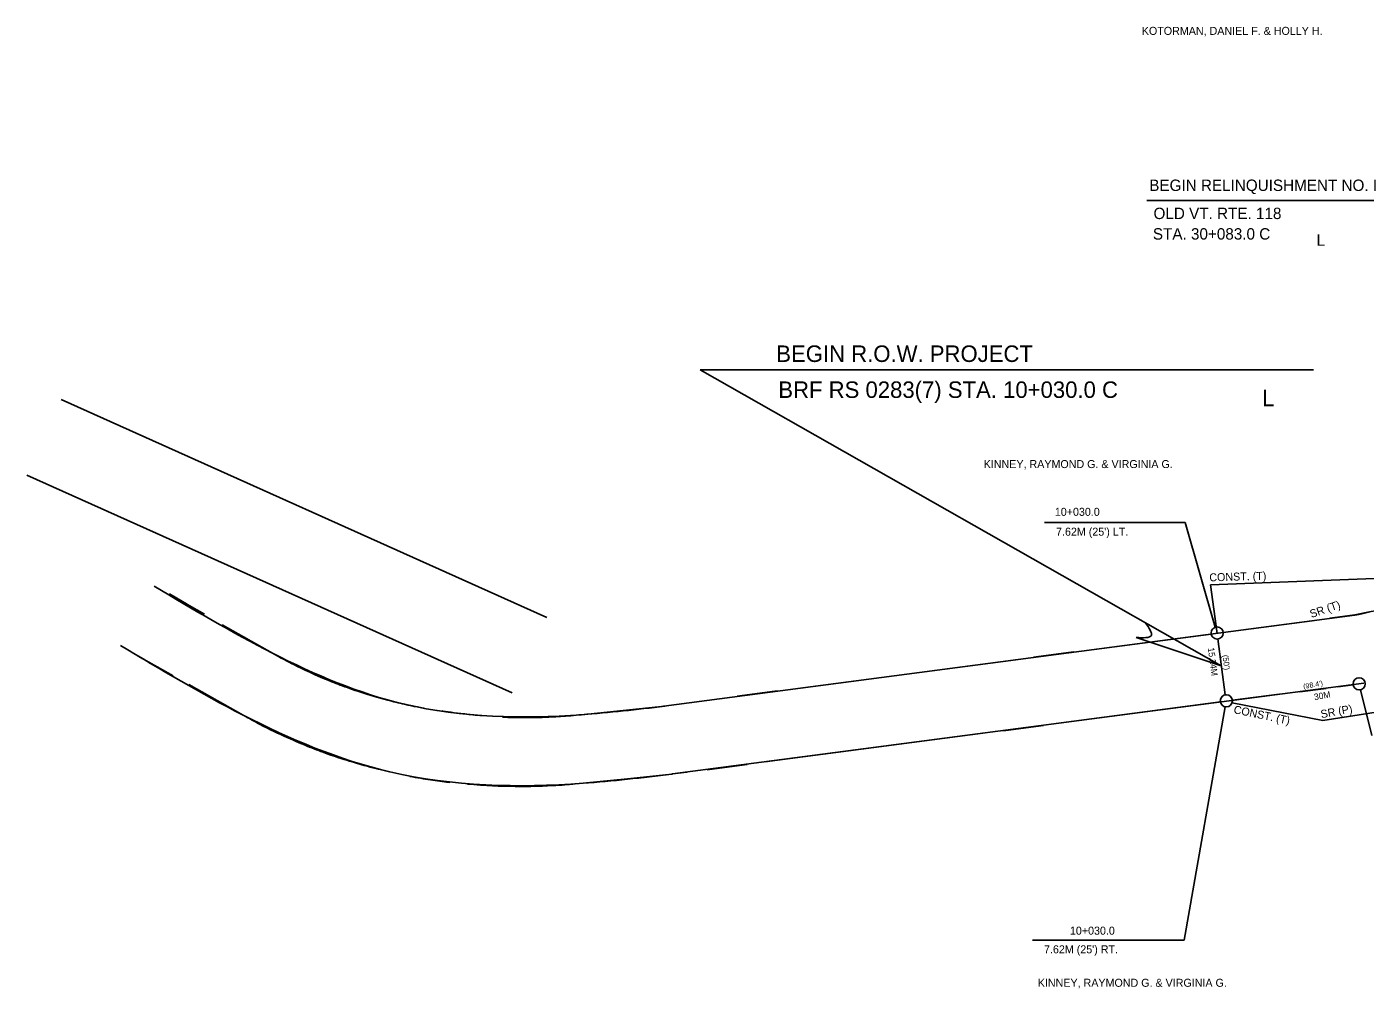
# Model space of a CAD drawing. Extents: x 624 to 1448, y 1599 to 1865.
# Drawn here: x 624.2 to 922.4, y 1625.2 to 1839.6 of the extents above; entities that cross this region are included whole.
import ezdxf

# ---------------------------------------------------------------- set-up
doc = ezdxf.new("R2010")
doc.units = 0
for name, color, linetype in [('C_I', 7, 'Continuous'), ('CPSM', 7, 'Continuous'), ('L_A', 7, 'Continuous'), ('L_C', 7, 'Continuous'), ('L_I', 7, 'Continuous'), ('Level 30', 7, 'Continuous'), ('ODIML_P', 7, 'Continuous')]:
    doc.layers.add(name, color=color, linetype=linetype)

msp = doc.modelspace()

# ---------------------------------------------------------------- linework, layer by layer
at = {"layer": 'CPSM'}
for p, q in [((873.74, 1800.82), (938.24, 1800.82)), ((890.3, 1697.02), (774.23, 1763.05)), ((774.23, 1763.05), (910.87, 1763.05)), ((890.3, 1697.02), (871.34, 1703.38))]:
    msp.add_line(p, q, dxfattribs=at)
msp.add_spline([(871.34, 1703.38), (874.77, 1703.83), (873.43, 1706.61)], degree=3, dxfattribs=at)
at = {"layer": 'L_C'}
for p, q in [((850.91, 1729.02), (882.29, 1729.02)), ((888.99, 1705.64), (882.29, 1729.02)), ((923.9, 1681.52), (921.37, 1691.66)), ((882.05, 1635.89), (891.19, 1687.94)), ((848.23, 1635.89), (882.05, 1635.89))]:
    msp.add_line(p, q, dxfattribs=at)
at = {"layer": 'L_I'}
msp.add_line((889.54, 1703.05), (891.21, 1690.61), dxfattribs=at)
for centre in [(889.43, 1704.37), (921.05, 1693.04), (891.46, 1689.26)]:
    msp.add_circle(centre, 1.35, dxfattribs=at)
at = {"layer": 'Level 30'}
for p, q in [((889.38, 1704.23), (887.94, 1715.13)), ((892.78, 1688.81), (912.99, 1684.83)), ((912.99, 1684.83), (951.45, 1690.95))]:
    msp.add_line(p, q, dxfattribs=at)
msp.add_lwpolyline([(960.91, 1717.94), (887.94, 1715.13)], dxfattribs=at)
at = {"layer": 'ODIML_P'}
for p, q in [((631.85, 1756.41), (740.03, 1707.85)), ((624.15, 1739.58), (732.33, 1691.02))]:
    msp.add_line(p, q, dxfattribs=at)
for points in [[(663.74, 1708.56), (655.92, 1713)], [(659.76, 1710.91), (655.96, 1713.07)], [(923.36, 1709.11), (920.08, 1708.4), (914.5, 1707.67)], [(712.73, 1687.57), (712.73, 1687.58), (712.18, 1687.68), (711.22, 1687.87), (710.5, 1688.01), (709.96, 1688.13), (709.15, 1688.3), (708.34, 1688.48), (707.85, 1688.59), (707.37, 1688.7), (706.9, 1688.81), (706.43, 1688.93), (705.98, 1689.04), (705.53, 1689.15), (704.64, 1689.38), (703.79, 1689.61), (702.97, 1689.83), (702.18, 1690.06), (701.41, 1690.28), (700.67, 1690.5), (699.96, 1690.72), (699.27, 1690.94), (698.6, 1691.15), (697.96, 1691.37), (697.34, 1691.58), (696.73, 1691.78), (696.15, 1691.99), (695.59, 1692.18), (695.05, 1692.38), (694.52, 1692.58), (694.02, 1692.76), (693.53, 1692.95), (693.06, 1693.13), (692.6, 1693.31), (692.16, 1693.49), (691.3, 1693.83), (690.5, 1694.16), (689.76, 1694.48), (689.06, 1694.78), (688.41, 1695.06), (687.8, 1695.34), (687.23, 1695.6), (686.7, 1695.84), (686.2, 1696.07), (685.74, 1696.29), (685.3, 1696.5), (684.49, 1696.9), (683.78, 1697.25), (683.16, 1697.57), (682.62, 1697.84), (682.15, 1698.09), (681.33, 1698.52), (680.72, 1698.85), (680.26, 1699.1), (679.58, 1699.48), (678.89, 1699.87), (667.72, 1706.22)], [(920.09, 1708.33), (766.09, 1688.06)], [(910.58, 1707.07), (890.77, 1704.47)], [(888.1, 1704.12), (861.97, 1700.68)], [(857.38, 1700.15), (848.47, 1698.98)], [(648.98, 1699.24), (656.8, 1694.8)], [(844.55, 1698.38), (795.94, 1691.99)], [(660.28, 1692.91), (672.34, 1686.06), (672.82, 1685.79), (673.29, 1685.53), (673.76, 1685.27), (674.22, 1685.02), (674.67, 1684.77), (675.11, 1684.54), (675.55, 1684.3), (675.99, 1684.07), (676.84, 1683.63), (677.68, 1683.2), (678.49, 1682.8), (679.27, 1682.41), (680.04, 1682.05), (680.78, 1681.7), (681.51, 1681.36), (682.21, 1681.04), (682.89, 1680.74), (683.56, 1680.44), (684.2, 1680.16), (684.83, 1679.9), (685.44, 1679.64), (686.03, 1679.4), (686.6, 1679.16), (687.16, 1678.94), (687.7, 1678.73), (688.23, 1678.52), (688.74, 1678.33), (689.23, 1678.14), (689.71, 1677.96), (690.18, 1677.79), (691.08, 1677.46), (691.94, 1677.16), (692.74, 1676.88), (693.49, 1676.63), (694.2, 1676.39), (694.87, 1676.18), (695.49, 1675.98), (696.08, 1675.8), (696.63, 1675.63), (697.15, 1675.47), (697.64, 1675.33), (698.56, 1675.06), (699.36, 1674.84), (700.07, 1674.64), (700.69, 1674.48), (701.23, 1674.33), (701.71, 1674.21), (702.54, 1674), (703.17, 1673.85), (704.12, 1673.62), (705.01, 1673.42)], [(768.08, 1672.95), (922.08, 1693.22)], [(791.36, 1691.46), (782.44, 1690.28)], [(907.84, 1691.27), (913.67, 1692.02)], [(916.32, 1692.36), (919.72, 1692.8)], [(778.52, 1689.69), (766.09, 1688.06), (766.31, 1688.05), (757.04, 1687.1), (747.77, 1686.15), (747.16, 1686.09), (746.55, 1686.03), (745.96, 1685.98), (745.37, 1685.93), (744.79, 1685.88), (744.23, 1685.84), (743.67, 1685.8), (743.12, 1685.76), (742.57, 1685.73), (742.04, 1685.69), (741.51, 1685.67), (741, 1685.64), (740.49, 1685.62), (739.98, 1685.6), (739, 1685.56), (738.04, 1685.54), (737.11, 1685.52), (736.21, 1685.51), (735.34, 1685.5), (734.5, 1685.5), (733.68, 1685.51), (732.88, 1685.52), (732.12, 1685.54), (731.37, 1685.56), (730.65, 1685.58), (730.17, 1685.6)], [(854.65, 1684.34), (890.16, 1689.02)], [(892.82, 1689.37), (903.25, 1690.74)], [(725.57, 1685.95), (725.11, 1685.99), (724.58, 1686.03), (724.07, 1686.08), (723.58, 1686.12), (722.63, 1686.22), (721.74, 1686.31), (720.9, 1686.41), (720.11, 1686.5), (719.38, 1686.6), (718.69, 1686.69), (718.04, 1686.78), (717.43, 1686.87), (716.87, 1686.95), (716.65, 1686.99)], [(841.82, 1682.58), (850.73, 1683.75)], [(788.62, 1675.65), (837.23, 1682.05)], [(722.36, 1670.69), (722.95, 1670.64), (723.74, 1670.58), (724.5, 1670.52), (725.24, 1670.47), (725.96, 1670.42), (726.65, 1670.38), (727.32, 1670.34), (727.97, 1670.31), (728.6, 1670.28), (729.21, 1670.25), (729.8, 1670.23), (730.38, 1670.22), (730.93, 1670.2), (731.47, 1670.19), (731.99, 1670.18), (733, 1670.16), (733.95, 1670.16), (734.83, 1670.16), (735.66, 1670.16), (736.44, 1670.17), (737.17, 1670.19), (737.86, 1670.2), (738.5, 1670.22), (739.1, 1670.24), (739.66, 1670.26), (740.19, 1670.29), (741.18, 1670.33), (742.05, 1670.38), (742.8, 1670.43), (743.47, 1670.47), (744.05, 1670.51), (745.06, 1670.59), (745.82, 1670.65), (746.39, 1670.7), (747.25, 1670.78), (748.1, 1670.86), (757.98, 1671.87), (767.86, 1672.88), (768.08, 1672.95), (771.2, 1673.36)], [(775.79, 1673.88), (784.7, 1675.06)], [(709.52, 1672.4), (709.53, 1672.4), (710.13, 1672.29), (710.73, 1672.18), (711.31, 1672.08), (711.89, 1671.98), (712.45, 1671.88), (713.01, 1671.79), (713.56, 1671.7), (714.1, 1671.62), (714.63, 1671.54), (715.15, 1671.46), (715.66, 1671.39), (716.68, 1671.25), (717.66, 1671.12), (718.41, 1671.03)]]:
    msp.add_lwpolyline(points, dxfattribs=at)
for points in [[(1003.36, 1746.6), (995.34, 1738.04), (983.91, 1729.6), (969.46, 1721.55), (951.06, 1715.09), (934.74, 1711.49), (920.09, 1708.33)], [(766.31, 1688.05), (747.77, 1686.15), (708.34, 1688.48), (678.89, 1699.87), (652.53, 1714.84)], [(645.01, 1701.59), (672.34, 1686.06), (705.07, 1673.4), (748.1, 1670.86), (767.86, 1672.88)]]:
    msp.add_spline(points, degree=3, dxfattribs=at)

# ---------------------------------------------------------------- texts
at = {"layer": 'C_I'}
for s, height, rotation, p in [('CONST. (T)', 1.783, 1.7533, (887.69, 1715.87)), ('SR (T)', 1.783, 18.8946, (910.41, 1707.7)), ('15.24M', 1.426, 277.6423, (887.33, 1701.03)), ("(50')", 1.284, 277.6423, (890.58, 1699.4)), ("(98.4')", 1.141, 10.4964, (908.7, 1691.87)), ('30M', 1.426, 10.4964, (911.12, 1689.36)), ('CONST. (T)', 1.783, 348.401, (892.98, 1686.5)), ('SR (P)', 1.783, 10.4964, (912.64, 1685.36))]:
    msp.add_text(s, height=height, rotation=rotation, dxfattribs=at).set_placement(p)
at = {"layer": 'CPSM'}
for s, height, p in [('BEGIN RELINQUISHMENT NO. I', 2.54, (874.28, 1802.94)), ('OLD VT. RTE. 118', 2.54, (875.23, 1796.67)), ('STA. 30+083.0 C', 2.54, (875.09, 1792.1)), ('L', 2.54, (911.56, 1790.72)), ('BEGIN R.O.W. PROJECT', 3.683, (791.17, 1764.81)), ('BRF RS 0283(7) STA. 10+030.0 C', 3.683, (791.62, 1756.79)), ('L', 3.68, (899.41, 1754.94))]:
    msp.add_text(s, height=height, dxfattribs=at).set_placement(p)
at = {"layer": 'L_A'}
for s, p in [('KOTORMAN, DANIEL F. & HOLLY H.', (872.62, 1837.75)), ('KINNEY, RAYMOND G. & VIRGINIA G.', (837.39, 1741.15)), ('KINNEY, RAYMOND G. & VIRGINIA G.', (849.44, 1625.48))]:
    msp.add_text(s, height=1.783, dxfattribs=at).set_placement(p)
at = {"layer": 'L_C'}
for s, p in [('10+030.0', (853.24, 1730.5)), ("7.62M (25') LT.", (853.51, 1726.07)), ('10+030.0', (856.6, 1637.1)), ("7.62M (25') RT.", (850.83, 1632.94))]:
    msp.add_text(s, height=1.783, dxfattribs=at).set_placement(p)

doc.saveas('drawing.dxf')
